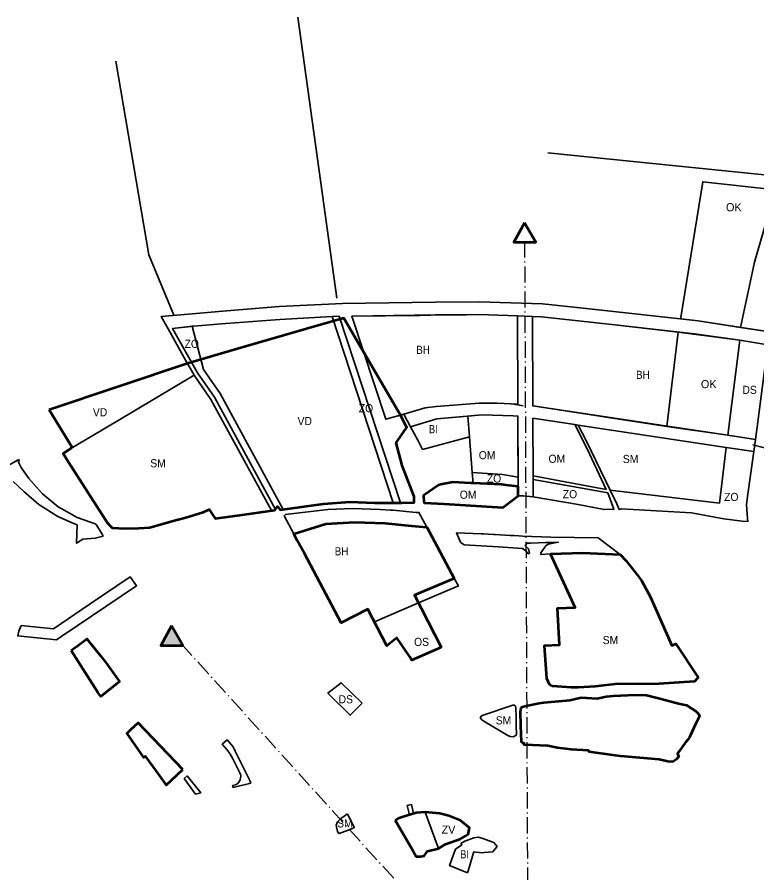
# Model space of a CAD drawing. Extents: x -650276 to -642489, y -1074311 to -1066720.
# Drawn here: x -647822 to -646730, y -1070373 to -1069110 of the extents above; entities that cross this region are included whole.
import ezdxf

# ---------------------------------------------------------------- set-up
doc = ezdxf.new("R2010")
doc.units = 0
doc.header["$LTSCALE"] = 4.8
doc.header["$PDMODE"] = 32
doc.header["$PDSIZE"] = 2.4
doc.linetypes.add('DOT_DASHED', pattern=[7.7, 5, -1.2, 0.3, -1.2])
for name, color, linetype, lineweight in [('1', 7, 'Continuous', 35), ('12', 7, 'Continuous', 35), ('13', 7, 'Continuous', 35), ('15', 7, 'Continuous', 35), ('18', 7, 'Continuous', 35), ('2', 7, 'Continuous', 35), ('24', 7, 'Continuous', 35), ('35', 7, 'Continuous', 35), ('40', 7, 'Continuous', 35), ('42', 7, 'Continuous', 35), ('54', 7, 'Continuous', 35), ('55', 7, 'Continuous', 53), ('60', 7, 'Continuous', 53), ('9', 7, 'Continuous', 35)]:
    doc.layers.add(name, color=color, linetype=linetype, lineweight=lineweight)
doc.layers.add('62', color=7, linetype='Continuous')

msp = doc.modelspace()

# ---------------------------------------------------------------- hatches: boundary and pattern name
at = {"layer": '55'}
msp.add_hatch(color=256, dxfattribs=at).paths.add_polyline_path([(-647593.545, -1070008.59), (-647609.496, -1070037.236), (-647577.112, -1070037.236)])

# ---------------------------------------------------------------- linework, layer by layer
at = {"layer": '1'}
for points in [[(-647251.002, -1069695.852), (-647219.628, -1069686.746), (-647203.374, -1069684.716), (-647139.649, -1069679.961), (-647113.255, -1069679.966), (-647082.761, -1069681.399), (-647083.356, -1069551.018), (-647140.247, -1069549.071), (-647158.572, -1069549.252), (-647211.05, -1069549.77), (-647227.623, -1069550.23), (-647327.682, -1069551.263), (-647277.71, -1069703.421)], [(-646944.168, -1069563.743), (-647047.648, -1069552.245), (-647061.304, -1069551.773), (-647060.7, -1069683.894), (-646863, -1069714), (-646846, -1069575)], [(-647365.866, -1069857.774), (-647413.461, -1069872.442), (-647343.28, -1070003.81), (-647339.69, -1070001.95), (-647330.5, -1069997.19), (-647304.05, -1069983.79), (-647294.257, -1070002.745), (-647229.096, -1069974.658), (-647235, -1069963), (-647176.499, -1069938.333), (-647205.781, -1069883.796), (-647217.177, -1069862.57), (-647243.231, -1069860.34), (-647278.525, -1069857.002), (-647323.794, -1069855.468)]]:
    msp.add_lwpolyline(points, close=True, dxfattribs=at)
at = {"layer": '12'}
for points in [[(-647150.138, -1069782.334), (-647105.334, -1069785.168), (-647082.271, -1069788.81), (-647082.682, -1069698.791), (-647089.456, -1069698.579), (-647135.585, -1069697.137), (-647156.782, -1069698.901), (-647154.33, -1069729.69)], [(-647060.23, -1069786.932), (-646952.56, -1069807.13), (-646980.4, -1069746.98), (-646998.56, -1069711.443), (-647060.617, -1069702.116)]]:
    msp.add_lwpolyline(points, close=True, dxfattribs=at)
for points in [[(-647107.04, -1069799.84), (-647148.9, -1069797.88), (-647148.9, -1069797.88), (-647178.73, -1069796.4), (-647196.616, -1069800.068)], [(-647196.616, -1069800.068), (-647199.65, -1069800.69), (-647221.87, -1069816.21), (-647221.28, -1069824.74), (-647221.14, -1069826.761), (-647191.66, -1069828.58), (-647201.106, -1069827.997), (-647191.66, -1069828.58), (-647104.741, -1069833.568)], [(-647082.206, -1069802.916), (-647107.04, -1069799.84), (-647107.04, -1069799.84)], [(-647104.741, -1069833.568), (-647082.145, -1069816.321), (-647082.206, -1069802.916)]]:
    msp.add_lwpolyline(points, dxfattribs=at)
at = {"layer": '13'}
for points in [[(-646816.615, -1069558.064), (-646754.066, -1069567.993), (-646733.74, -1069471.688), (-646733.74, -1069471.688), (-646702.425, -1069364.771), (-646702.425, -1069364.771), (-646702.425, -1069364.771), (-646702.425, -1069364.771), (-646702.425, -1069364.771), (-646809.879, -1069353.002), (-646842.103, -1069553.182), (-646842.441, -1069555.283), (-646816.615, -1069558.064)], [(-646772.906, -1069727.176), (-646755.269, -1069587.04), (-646846, -1069575), (-646863, -1069714)]]:
    msp.add_lwpolyline(points, close=True, dxfattribs=at)
at = {"layer": '15'}
for points in [[(-646711.442, -1069574.759), (-646816.615, -1069558.064), (-646910.029, -1069548.006), (-646986.633, -1069539.757), (-647046.325, -1069533.275), (-647140.008, -1069530.068), (-647204.293, -1069530.647), (-647341.697, -1069532.602), (-647434.969, -1069537.141), (-647523.931, -1069544.499), (-647568.792, -1069548.21), (-647608.81, -1069551.868), (-647598.735, -1069570.026), (-647573.15, -1069616.16), (-647570.37, -1069621.18), (-647560.36, -1069638.39), (-647535.588, -1069674.163), (-647446.322, -1069838.338), (-647441.19, -1069837.6), (-647440.46, -1069836.558), (-647530.471, -1069671.013), (-647555.266, -1069635.207), (-647592.199, -1069569.411), (-647560.836, -1069566.036), (-647514.067, -1069562.282), (-647513.66, -1069562.249), (-647433.779, -1069556.106), (-647433.779, -1069556.106), (-647356.899, -1069552.034), (-647346.554, -1069551.486), (-647256.034, -1069827.107), (-647235.49, -1069826.51), (-647235.62, -1069817.62), (-647253.45, -1069771.95), (-647262.46, -1069738.25), (-647259.11, -1069733.52), (-647253.97, -1069726.27), (-647246.42, -1069715.63), (-647249.555, -1069709.677), (-647256.061, -1069697.32), (-647277.71, -1069703.421), (-647327.682, -1069551.263), (-647204.208, -1069549.647), (-647140.247, -1069549.071), (-647083.356, -1069551.018), (-647061.304, -1069551.773), (-647047.702, -1069552.239), (-646944.167, -1069563.743), (-646822.169, -1069577.72), (-646755.269, -1069587.04), (-646714.037, -1069593.585)], [(-647083.356, -1069551.018), (-647082.761, -1069681.399), (-647113.255, -1069679.966), (-647139.649, -1069679.961), (-647203.374, -1069684.716), (-647219.628, -1069686.746), (-647251.002, -1069695.852), (-647240.994, -1069714.513), (-647202.181, -1069702.678), (-647135.585, -1069697.137), (-647089.456, -1069698.579), (-647082.682, -1069698.791), (-647082.145, -1069816.321)], [(-647060.617, -1069702.116), (-646998.56, -1069711.443), (-646993.771, -1069712.163), (-646775.286, -1069745.022), (-646734.48, -1069751.35), (-646732.143, -1069733.308), (-646772.906, -1069727.176), (-646842.148, -1069716.763), (-647060.7, -1069683.894), (-647061.304, -1069551.773), (-647083.356, -1069551.018)], [(-647082.145, -1069816.321), (-647082.145, -1069816.321), (-647074.72, -1069816.8), (-647060.029, -1069817.854), (-647060.206, -1069792.294), (-647060.23, -1069786.932), (-647060.617, -1069702.116)], [(-647082.206, -1069802.916), (-647107.04, -1069799.84), (-647148.9, -1069797.88), (-647148.9, -1069797.88), (-647178.73, -1069796.4), (-647196.616, -1069800.068)], [(-647196.616, -1069800.068), (-647199.65, -1069800.69), (-647221.87, -1069816.21), (-647221.28, -1069824.74), (-647221.14, -1069826.761), (-647205.603, -1069827.72), (-647191.66, -1069828.58), (-647201.106, -1069827.997), (-647191.66, -1069828.58), (-647104.741, -1069833.568)], [(-647104.741, -1069833.568), (-647082.145, -1069816.321), (-647082.206, -1069802.916)], [(-646931.67, -1069902.89), (-646964.111, -1069878.315), (-647034.195, -1069877.629), (-647076, -1069875.85), (-647081.25, -1069875.56), (-647081.26, -1069875.76), (-647088.94, -1069875.34), (-647088.93, -1069875.14), (-647094.24, -1069874.85), (-647116.31, -1069873.65), (-647118.77, -1069873.51), (-647133.58, -1069872.73), (-647136.94, -1069872.55), (-647173.23, -1069871.09), (-647167.14, -1069884.85)], [(-647167.14, -1069884.85), (-647166.8, -1069885.63), (-647163.55, -1069887.98), (-647162.03, -1069888.89), (-647111.76, -1069891.77)], [(-647068.2, -1069902.28), (-647065.47, -1069901.09), (-647067.02, -1069894.68), (-647071.73, -1069890.39), (-647070.87, -1069888.71), (-647069.57, -1069886.35), (-647064.32, -1069886.23), (-647041.25, -1069885.62), (-647035.6, -1069885.43), (-647023.04, -1069885), (-647035.53, -1069887.44), (-647037.79, -1069887.88), (-647041.47, -1069890.42), (-647042.75, -1069892.14), (-647046.49, -1069897.19), (-647048.8, -1069900.51), (-647048.67, -1069903.32), (-647034.51, -1069902.21)], [(-647111.76, -1069891.77), (-647075.97, -1069894.33), (-647071, -1069897.87), (-647068.2, -1069902.28)], [(-647034.51, -1069902.21), (-647032.16, -1069902.13), (-646987.56, -1069900.52), (-646931.67, -1069902.89)]]:
    msp.add_lwpolyline(points, dxfattribs=at)
for points in [[(-647217.177, -1069862.57), (-647228.77, -1069840.98), (-647232.66, -1069841.07), (-647266.62, -1069837.86), (-647270.71, -1069837.61), (-647285.9, -1069836.66), (-647326.71, -1069835.46), (-647363.21, -1069836.64), (-647425.73, -1069844.31), (-647427.62, -1069845.94), (-647413.461, -1069872.442), (-647365.866, -1069857.774), (-647323.794, -1069855.468), (-647278.525, -1069857.002), (-647239.912, -1069860.654)], [(-647815.788, -1070007.72), (-647767.622, -1070012.66), (-647714.989, -1069977.087), (-647654.577, -1069936.255), (-647645.274, -1069949.279), (-647755.356, -1070023.682), (-647763.476, -1070029.17), (-647820.515, -1070023.319), (-647818.81, -1070016.41)], [(-647235, -1069963), (-647176.499, -1069938.333), (-647170.546, -1069949.42), (-647229.096, -1069974.658)], [(-647493.13, -1070225.217), (-647492.138, -1070227.681), (-647491.692, -1070229.974), (-647491.767, -1070233.217), (-647492.286, -1070235.393), (-647493.254, -1070237.6), (-647495.889, -1070240.926), (-647499.448, -1070243.223), (-647503.6, -1070243.95), (-647502.82, -1070246.91), (-647476.94, -1070240.79), (-647477.78, -1070237.42), (-647484.35, -1070223.91), (-647491.97, -1070208.95), (-647499.68, -1070193.54), (-647502.99, -1070186.94), (-647511.73, -1070176.61), (-647518.813, -1070183.069), (-647512.222, -1070190.785), (-647509.223, -1070194.61), (-647507.054, -1070197.854), (-647505.688, -1070200.172), (-647504.419, -1070202.575)], [(-647575.15, -1070233.71), (-647570.887, -1070229.877), (-647550.603, -1070254.911), (-647558.19, -1070256.86)], [(-647575.15, -1070233.71), (-647558.19, -1070256.86), (-647550.603, -1070254.911), (-647570.887, -1070229.877)], [(-647242.698, -1070287.238), (-647236.567, -1070285.154), (-647239.781, -1070272.031), (-647242.06, -1070272.35), (-647246.28, -1070273.733)]]:
    msp.add_lwpolyline(points, close=True, dxfattribs=at)
at = {"layer": '18'}
for points in [[(-647560.36, -1069638.39), (-647674.901, -1069706.701), (-647742.36, -1069746.93)], [(-647446.322, -1069838.338), (-647535.588, -1069674.163), (-647560.36, -1069638.39)], [(-647742.36, -1069746.93), (-647752.32, -1069752.95), (-647753.7, -1069753.9)], [(-647753.7, -1069753.9), (-647751.66, -1069757.12), (-647745.84, -1069766.71), (-647737.17, -1069780.85), (-647700.58, -1069837.2), (-647687.45, -1069857.15), (-647681.51, -1069863.72)], [(-647641.78, -1069864.26), (-647625.83, -1069863.19), (-647593.07, -1069853.74), (-647583.62, -1069851.13), (-647572.63, -1069848.63), (-647559.47, -1069844.92), (-647547.12, -1069840.87), (-647538.34, -1069836.68), (-647536.82, -1069838.87), (-647531.33, -1069847.23), (-647529.5, -1069849.99), (-647500.03, -1069846.28), (-647492.76, -1069845.02), (-647446.322, -1069838.338)], [(-647681.51, -1069863.72), (-647661.79, -1069864.92), (-647641.78, -1069864.26)]]:
    msp.add_lwpolyline(points, dxfattribs=at)
for points in [[(-646785.437, -1069827.534), (-646775.286, -1069745.022), (-646993.771, -1069712.163), (-646981.92, -1069734.86), (-646946.369, -1069808.291)], [(-647032.16, -1069902.13), (-647034.51, -1069902.21), (-646998.06, -1069981.49), (-647024.05, -1069982.48), (-647021.27, -1070036.28), (-647043.25, -1070037.29), (-647040.12, -1070086.11), (-647036.03, -1070094.96), (-647034.17, -1070096.49), (-647031.73, -1070097.21), (-647003.49, -1070099.66), (-646993.92, -1070099.49), (-646968.89, -1070098.02), (-646934.63, -1070094.24), (-646904.97, -1070094.52), (-646874.9, -1070094.1), (-646859.29, -1070093.1), (-646821.89, -1070090.7), (-646817.15, -1070084.76), (-646816.9, -1070084.45), (-646837.65, -1070053.22), (-646849.79, -1070035.17), (-646855.62, -1070037.66), (-646886.85, -1069966.26), (-646900.26, -1069941.64), (-646904.72, -1069935.84), (-646922.79, -1069912.31), (-646931.67, -1069902.89), (-646987.56, -1069900.52)], [(-647097.63, -1070170.37), (-647093.89, -1070171.55), (-647089.47, -1070172.21), (-647086.62, -1070170.89), (-647084.98, -1070169.29), (-647085.17, -1070154.78), (-647085.24, -1070144.07), (-647085.62, -1070128.24), (-647086.49, -1070126.62), (-647088.08, -1070125.63), (-647090.2, -1070125.64), (-647133.96, -1070140.44), (-647136.65, -1070141.75), (-647137.99, -1070143.09), (-647137.96, -1070144.66), (-647136.09, -1070146.97), (-647132.95, -1070149.08)], [(-647333.87, -1070285.66), (-647324.11, -1070306.21), (-647324.94, -1070306.63), (-647327.18, -1070307.52), (-647333.97, -1070310.22), (-647346.97, -1070315.05), (-647349, -1070312), (-647350.67, -1070302.55), (-647348.677, -1070297.894), (-647345.27, -1070293.99), (-647343.9, -1070292.96), (-647337.56, -1070288.43), (-647334.91, -1070286.51)]]:
    msp.add_lwpolyline(points, close=True, dxfattribs=at)
msp.add_point((-647687.45, -1069857.15), dxfattribs=at)
at = {"layer": '2'}
msp.add_lwpolyline([(-647223.66, -1069748.26), (-647154.33, -1069729.69), (-647156.782, -1069698.901), (-647202.181, -1069702.678), (-647240.994, -1069714.513), (-647230.16, -1069734.42)], close=True, dxfattribs=at)
for points in [[(-647167.03, -1070329.81), (-647165.36, -1070331.59), (-647174.81, -1070338.01), (-647183.55, -1070362.35), (-647156.9, -1070372.69)], [(-647113.37, -1070333.96), (-647118.28, -1070328.29), (-647135.94, -1070321.54), (-647140.83, -1070320.47), (-647147.66, -1070321.04), (-647161.17, -1070326.29), (-647167.03, -1070329.81)], [(-647156.9, -1070372.69), (-647154.31, -1070363.46), (-647151.09, -1070353.15), (-647147.6, -1070341.95), (-647144.57, -1070342.42), (-647139.84, -1070343.16), (-647135.62, -1070343.32), (-647132.49, -1070342.91)], [(-647132.49, -1070342.91), (-647119.88, -1070342.1), (-647116.03, -1070337.68), (-647113.37, -1070333.96)]]:
    msp.add_lwpolyline(points, dxfattribs=at)
at = {"layer": '24'}
msp.add_line((-646772.907, -1069727.177), (-646732.143, -1069733.308), dxfattribs=at)
for points in [[(-646660.526, -1069369.36), (-646702.425, -1069364.771), (-646733.74, -1069471.688), (-646754.066, -1069567.993), (-646711.442, -1069574.759), (-646704.68, -1069533.06), (-646699.07, -1069500.57), (-646690.51, -1069466.97), (-646681.5, -1069434.17)], [(-647312.485, -1070122.583), (-647329.932, -1070140.465), (-647334.81, -1070135.73), (-647357.4, -1070113.69), (-647359.8, -1070111.34), (-647362.87, -1070107.74), (-647343.454, -1070092.368)]]:
    msp.add_lwpolyline(points, close=True, dxfattribs=at)
for points in [[(-646725.82, -1069684.5), (-646714.037, -1069593.585), (-646755.269, -1069587.04), (-646772.907, -1069727.177)], [(-646732.143, -1069733.308), (-646725.82, -1069684.5), (-646725.82, -1069684.5)]]:
    msp.add_lwpolyline(points, dxfattribs=at)
at = {"layer": '35'}
for points in [[(-647356.899, -1069552.034), (-647433.779, -1069556.106), (-647433.779, -1069556.106), (-647513.66, -1069562.249), (-647514.067, -1069562.282), (-647560.836, -1069566.036), (-647563.104, -1069566.28)], [(-647369.3, -1069828.22), (-647330.46, -1069825.51), (-647294.38, -1069826.88), (-647270.09, -1069827.02), (-647266.581, -1069827.042), (-647356.899, -1069552.034)], [(-647563.104, -1069566.28), (-647546.777, -1069629.901), (-647521.943, -1069665.763)], [(-647521.943, -1069665.763), (-647428.993, -1069836.714), (-647369.3, -1069828.22)]]:
    msp.add_lwpolyline(points, dxfattribs=at)
msp.add_lwpolyline([(-647740.74, -1069744.24), (-647742.36, -1069746.93), (-647674.901, -1069706.701), (-647560.36, -1069638.39), (-647570.37, -1069621.18), (-647701.61, -1069665.279), (-647774.11, -1069689.64)], close=True, dxfattribs=at)
at = {"layer": '40'}
msp.add_lwpolyline([(-647199.79, -1070337.21), (-647189.63, -1070330.53), (-647167.43, -1070322.66), (-647155.89, -1070316.51), (-647154.23, -1070306.63), (-647167.15, -1070295.69), (-647184.77, -1070288.73), (-647197.68, -1070285.3), (-647219.36, -1070283.36)], close=True, dxfattribs=at)
at = {"layer": '42'}
msp.add_line((-647266.581, -1069827.042), (-647256.034, -1069827.107), dxfattribs=at)
for points in [[(-647256.034, -1069827.107), (-647346.554, -1069551.486), (-647356.899, -1069552.034), (-647266.581, -1069827.042)], [(-647827.16, -1069795.32), (-647811.83, -1069810.39), (-647789.55, -1069829.12), (-647761.54, -1069847.24), (-647740.46, -1069856.29), (-647733.06, -1069859.46), (-647733.71, -1069886.65), (-647724.35, -1069880.48), (-647706.39, -1069878.81), (-647694.63, -1069876.07), (-647696.25, -1069873.35), (-647704.99, -1069858.7), (-647706.44, -1069857.98), (-647732.93, -1069848.5), (-647752.25, -1069837.95), (-647760.79, -1069832.61), (-647783.96, -1069813.49), (-647792.84, -1069803.65), (-647804.02, -1069791.01), (-647815.36, -1069774.66), (-647819.78, -1069765.84), (-647818.28, -1069764.99), (-647818.73, -1069763.53), (-647820.09, -1069763.65), (-647838, -1069773.63)], [(-647082.271, -1069788.81), (-647105.334, -1069785.168), (-647105.334, -1069785.168), (-647150.138, -1069782.334), (-647148.9, -1069797.88), (-647107.04, -1069799.84)], [(-647107.04, -1069799.84), (-647082.206, -1069802.916), (-647082.271, -1069788.81)]]:
    msp.add_lwpolyline(points, dxfattribs=at)
for points in [[(-647555.266, -1069635.207), (-647530.471, -1069671.013), (-647440.46, -1069836.558), (-647437.46, -1069832.27), (-647433.32, -1069837.33), (-647428.993, -1069836.714), (-647521.943, -1069665.763), (-647546.777, -1069629.901), (-647563.104, -1069566.28), (-647592.199, -1069569.411)], [(-646775.286, -1069745.022), (-646785.437, -1069827.534), (-646946.369, -1069808.291), (-646936.6, -1069828.47), (-646933.39, -1069836.51), (-646929.67, -1069835.68), (-646826.63, -1069841.84), (-646778.74, -1069850.44), (-646751.8, -1069853.72), (-646743.31, -1069854.26), (-646743.7, -1069850.07), (-646745.56, -1069829.84), (-646743.85, -1069817.72), (-646734.48, -1069751.35)], [(-646993.81, -1069829.12), (-646993.81, -1069829.12), (-646955.45, -1069836.93), (-646940.94, -1069836.34), (-646950.08, -1069812.16), (-646952.68, -1069811.69), (-647060.206, -1069792.294), (-647060.029, -1069817.854)]]:
    msp.add_lwpolyline(points, close=True, dxfattribs=at)
at = {"layer": '54'}
for p, q in [((-647407.408, -1069110.064), (-647349.831, -1069524.717)), ((-646251.153, -1069390.558), (-647038.68, -1069310.312)), ((-647091.408, -1069680.918), (-647074.799, -1069683.763)), ((-646736.301, -1069741.493), (-646587.205, -1069778.112))]:
    msp.add_line(p, q, dxfattribs=at)
msp.add_lwpolyline([(-647675.801, -1069174.849), (-647627, -1069461), (-647590.168, -1069549.978)], dxfattribs=at)
at = {"layer": '55', "linetype": 'DOT_DASHED', "lineweight": 25}
for p, q in [((-647072.859, -1069440.93), (-647067.564, -1070600.224)), ((-647067.564, -1070600.224), (-647577.112, -1070037.236))]:
    msp.add_line(p, q, dxfattribs=at)
at = {"layer": '55'}
for points in [[(-647072.884, -1069413.607), (-647088.835, -1069442.253), (-647056.451, -1069442.253)], [(-647593.545, -1070008.59), (-647609.496, -1070037.236), (-647577.112, -1070037.236)]]:
    msp.add_lwpolyline(points, close=True, dxfattribs=at)
at = {"layer": '60'}
for points in [[(-647774.11, -1069689.64), (-647740.74, -1069744.24), (-647742.36, -1069746.93), (-647753.7, -1069753.9), (-647745.84, -1069766.71), (-647687.45, -1069857.15), (-647681.51, -1069863.72), (-647661.79, -1069864.92), (-647641.78, -1069864.26), (-647625.83, -1069863.19), (-647593.07, -1069853.74), (-647572.63, -1069848.63), (-647547.12, -1069840.87), (-647538.34, -1069836.68), (-647531.33, -1069847.23), (-647529.5, -1069849.99), (-647492.76, -1069845.02), (-647441.19, -1069837.6), (-647437.46, -1069832.27), (-647433.32, -1069837.33), (-647369.3, -1069828.22), (-647330.46, -1069825.51), (-647294.38, -1069826.88), (-647270.09, -1069827.02), (-647253.88, -1069827.12), (-647236.5, -1069826.63), (-647235.49, -1069826.51), (-647235.62, -1069817.62), (-647253.45, -1069771.95), (-647262.46, -1069738.25), (-647253.97, -1069726.27), (-647247.86, -1069717.66), (-647246.42, -1069715.63), (-647256.061, -1069697.32), (-647339.58, -1069554.46), (-647375.71, -1069564.91), (-647499.63, -1069600.73), (-647570.37, -1069621.18)], [(-647196.616, -1069800.068), (-647199.65, -1069800.69), (-647221.87, -1069816.21), (-647221.28, -1069824.74), (-647221.14, -1069826.761), (-647201.106, -1069827.997), (-647191.66, -1069828.58), (-647104.741, -1069833.568), (-647082.145, -1069816.321), (-647082.206, -1069802.916), (-647096.39, -1069801.15), (-647107.04, -1069799.84), (-647148.9, -1069797.88), (-647152.39, -1069797.7), (-647178.73, -1069796.4)], [(-647408.115, -1069882.449), (-647413.461, -1069872.442), (-647365.866, -1069857.774), (-647323.794, -1069855.468), (-647278.525, -1069857.002), (-647239.912, -1069860.654), (-647217.177, -1069862.57), (-647205.781, -1069883.796), (-647176.499, -1069938.333), (-647235, -1069963), (-647195.933, -1070040.107), (-647200.796, -1070042.246), (-647238.99, -1070059.05), (-647238.99, -1070059.05), (-647242.362, -1070054.067), (-647261.27, -1070026.12), (-647276, -1070038.08), (-647304.05, -1069983.79), (-647343.28, -1070003.81), (-647397.738, -1069901.873)], [(-647034.51, -1069902.21), (-646987.56, -1069900.52), (-646931.67, -1069902.89), (-646922.79, -1069912.31), (-646904.72, -1069935.84), (-646900.26, -1069941.64), (-646886.85, -1069966.26), (-646855.62, -1070037.66), (-646849.79, -1070035.17), (-646816.9, -1070084.45), (-646821.89, -1070090.7), (-646874.9, -1070094.1), (-646904.97, -1070094.52), (-646934.63, -1070094.24), (-646968.89, -1070098.02), (-646993.92, -1070099.49), (-647003.49, -1070099.66), (-647031.73, -1070097.21), (-647034.17, -1070096.49), (-647036.03, -1070094.96), (-647040.12, -1070086.11), (-647043.25, -1070037.29), (-647021.27, -1070036.28), (-647024.05, -1069982.48), (-646998.06, -1069981.49)], [(-647741.98, -1070044.74), (-647737.34, -1070041.32), (-647732.47, -1070037.73), (-647718.564, -1070027.479), (-647698.172, -1070052.962), (-647690.674, -1070062.331), (-647683.145, -1070072.735), (-647673.357, -1070086.635), (-647670.687, -1070090.426), (-647697.889, -1070112.941), (-647702.57, -1070106.56), (-647704.02, -1070104.5)], [(-647076.99, -1070128.48), (-647075.81, -1070127.72), (-647070.7, -1070126.64), (-647051.14, -1070122.49), (-647044.19, -1070121.78), (-647005.97, -1070117.89), (-646989.24, -1070114.17), (-646989.24, -1070114.17), (-646965.6, -1070115.74), (-646952.66, -1070112.57), (-646941.99, -1070111.74), (-646920.68, -1070110.58), (-646904.66, -1070110.24), (-646892.87, -1070110.82), (-646873.5, -1070115.8), (-646845.78, -1070122.84), (-646834.04, -1070125.34), (-646825.4, -1070130.78), (-646820.35, -1070134.43), (-646816.06, -1070138.5), (-646814.53, -1070141.96), (-646820.51, -1070153.68), (-646827.95, -1070169.52), (-646829.87, -1070173.61), (-646832.62, -1070177.08), (-646836.06, -1070181.31), (-646845.76, -1070194.67), (-646847.17, -1070197.38), (-646845.3, -1070201.3), (-646849.15, -1070205.9), (-646853.67, -1070208.44), (-646859.54, -1070209.09), (-646863.66, -1070208.37), (-646874.04, -1070205.5), (-646931.25, -1070200.56), (-646938.98, -1070199.89), (-646977.7, -1070194.45), (-646977.7, -1070193.62), (-646978.72, -1070193.6), (-646978.73, -1070192.54), (-647003.89, -1070190.89), (-647024.2, -1070188.68), (-647038.31, -1070185.73), (-647061.2, -1070184.6), (-647073.35, -1070184.01), (-647073.42, -1070181.47), (-647075.42, -1070181.53), (-647076.83, -1070180.73), (-647077.39, -1070179.57), (-647078.23, -1070155.29), (-647078.72, -1070135.49), (-647078.54, -1070132.1), (-647078.05, -1070129.8)], [(-647576.812, -1070220.636), (-647642.855, -1070151.617), (-647648.73, -1070157.05), (-647653.52, -1070161.48), (-647659.831, -1070167.317), (-647635.1, -1070202.5), (-647632.56, -1070200.72), (-647616.6, -1070223), (-647601.726, -1070243.764)], [(-647263.72, -1070295.43), (-647237.57, -1070340.12), (-647232.55, -1070348.65), (-647226.24, -1070348.88), (-647220.9, -1070348.04), (-647216.16, -1070340.99), (-647199.79, -1070337.21), (-647189.63, -1070330.53), (-647167.43, -1070322.66), (-647155.89, -1070316.51), (-647154.23, -1070306.63), (-647167.15, -1070295.69), (-647184.77, -1070288.73), (-647197.68, -1070285.3), (-647219.36, -1070283.36), (-647232.87, -1070284.15), (-647253.53, -1070290.92), (-647259.22, -1070292.91)]]:
    msp.add_lwpolyline(points, close=True, dxfattribs=at)
at = {"layer": '9'}
msp.add_lwpolyline([(-647261.27, -1070026.12), (-647238.99, -1070059.05), (-647195.933, -1070040.107), (-647229.096, -1069974.658), (-647294.257, -1070002.745), (-647276, -1070038.08)], close=True, dxfattribs=at)

# ---------------------------------------------------------------- texts
at = {"layer": '62'}
for s, p in [('OK', (-646775.694, -1069396.644)), ('OK', (-646812.694, -1069657.644)), ('ZV', (-647195.386, -1070315.148))]:
    msp.add_text(s, height=12, dxfattribs=at).set_placement(p)
for s, width, p in [('ZO', 0.95, (-647574.423, -1069598.188)), ('BH', 0.9, (-647232.617, -1069607.053)), ('BH', 0.9, (-646908.386, -1069643.937)), ('DS', 0.95, (-646751.423, -1069666.188)), ('ZO', 0.95, (-647317.423, -1069693.188)), ('VD', 0.95, (-647709.767, -1069699.204)), ('VD', 0.95, (-647407.767, -1069712.204)), ('BI', 0.85, (-647213.92, -1069724.163)), ('OM', 0.95, (-647140.377, -1069762.527)), ('OM', 0.95, (-647037.483, -1069767.845)), ('SM', 0.95, (-646927.837, -1069768.153)), ('SM', 0.95, (-647625.077, -1069774.464)), ('ZO', 0.95, (-647128.473, -1069797.058)), ('OM', 0.95, (-647168.433, -1069820.895)), ('ZO', 0.95, (-647016.473, -1069820.058)), ('ZO', 0.95, (-646778.423, -1069824.188)), ('BH', 0.9, (-647352.947, -1069904.358)), ('OS', 0.95, (-647235.865, -1070038.102)), ('SM', 0.95, (-646957.615, -1070035.352)), ('DS', 0.95, (-647347.216, -1070122.778)), ('SM', 0.95, (-647115.357, -1070153.941)), ('SM', 0.95, (-647349.357, -1070305.941)), ('BI', 0.85, (-647167.828, -1070351.569))]:
    msp.add_text(s, height=12, dxfattribs=dict(at, width=width)).set_placement(p)

doc.saveas('drawing.dxf')
